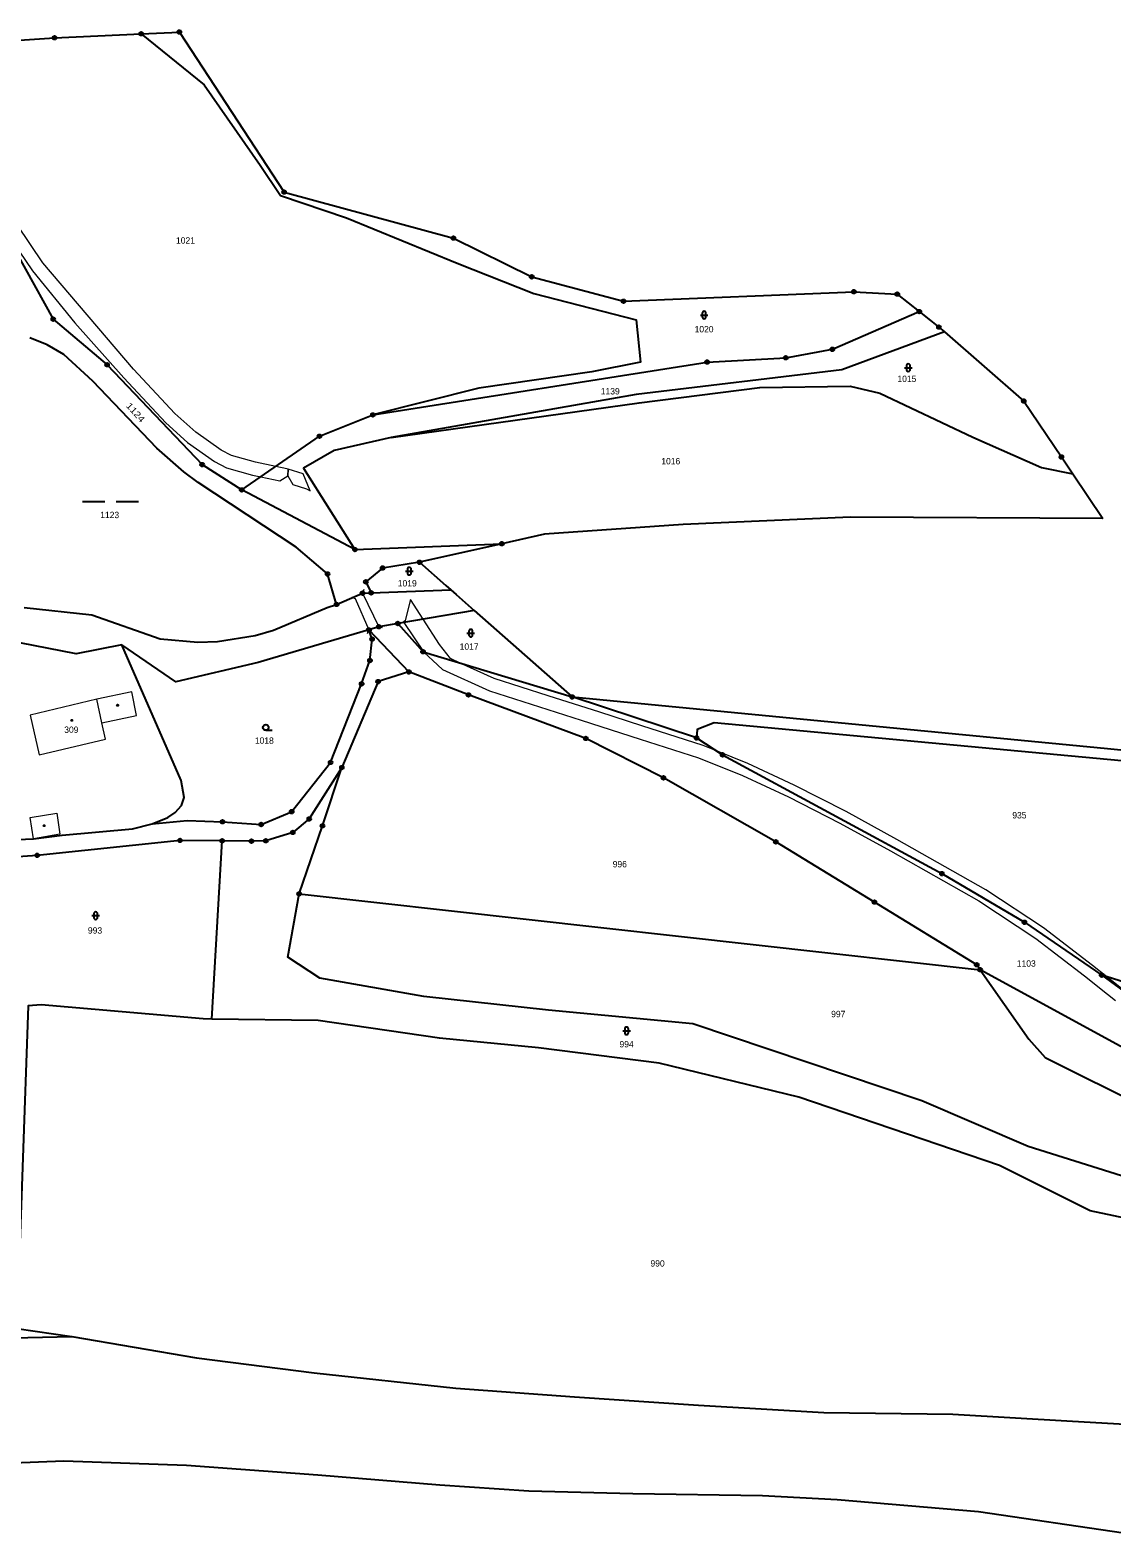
# Model space of a CAD drawing. Extents: x -758887 to -754328, y -1031688 to -1029144.
# Drawn here: x -757288.4 to -756999.4, y -1029651.7 to -1029248.7 of the extents above; entities that cross this region are included whole.
import ezdxf
from ezdxf.enums import TextEntityAlignment as Align

# ---------------------------------------------------------------- set-up
doc = ezdxf.new("R2010")
doc.units = 0
doc.header["$LTSCALE"] = 0.68
for name, color, linetype, lineweight in [('1', 7, 'Continuous', 25), ('13', 7, 'Continuous', 13), ('3', 7, 'Continuous', 25), ('4', 7, 'Continuous', 13), ('5', 7, 'Continuous', 25), ('8', 7, 'Continuous', 25)]:
    doc.layers.add(name, color=color, linetype=linetype, lineweight=lineweight)
doc.layers.add('2', color=7, linetype='Continuous')

msp = doc.modelspace()

# ---------------------------------------------------------------- linework, layer by layer
at = {"layer": '1'}
for p, q in [((-757050.84, -1029323.95), (-757047.83, -1029326.34)), ((-757047.83, -1029326.34), (-757045.61, -1029328.1)), ((-757045.61, -1029328.1), (-757044.12, -1029329.4)), ((-757201.64, -1029387.56), (-757231.92, -1029371.61)), ((-757201.64, -1029387.56), (-757162.39, -1029385.99)), ((-757184.38, -1029390.96), (-757177.34, -1029397.17)), ((-757177.34, -1029397.17), (-757176.07, -1029398.29)), ((-757197.3, -1029399.12), (-757176.07, -1029398.29)), ((-757176.07, -1029398.29), (-757174.58, -1029399.61)), ((-757174.58, -1029399.61), (-757169.82, -1029403.81)), ((-757169.82, -1029403.81), (-757190.2, -1029407.32)), ((-757169.82, -1029403.81), (-757157.88, -1029414.34)), ((-757197.9, -1029409.05), (-757187.23, -1029420.28)), ((-757157.88, -1029414.34), (-757143.59, -1029426.95)), ((-757110.36, -1029437.91), (-757143.59, -1029426.95)), ((-757239.88, -1029513.02), (-757237.12, -1029465.41)), ((-757216.56, -1029479.58), (-757034.58, -1029499.84)), ((-757292.02, -1029595.7), (-757277.31, -1029597.89))]:
    msp.add_line(p, q, dxfattribs=at)
for points in [[(-757304.11, -1029252.23), (-757303.67, -1029253.33), (-757322.82, -1029259.01), (-757313.65, -1029271.95), (-757297.2, -1029299.28), (-757282.28, -1029325.98), (-757267.89, -1029338.18), (-757242.47, -1029364.86), (-757231.92, -1029371.61)], [(-757299.48, -1029251.93), (-757281.9, -1029250.79), (-757258.78, -1029249.72), (-757248.58, -1029249.25)], [(-757258.78, -1029249.72), (-757241.93, -1029263.35), (-757226.99, -1029284.82), (-757221.56, -1029292.95), (-757203.95, -1029298.89), (-757174.34, -1029311.03), (-757153.81, -1029319.14), (-757126.48, -1029326.17), (-757125.36, -1029337.45), (-757138.34, -1029340.07), (-757168.55, -1029344.46), (-757196.86, -1029351.58)], [(-757248.58, -1029249.25), (-757220.58, -1029292.03), (-757175.35, -1029304.33), (-757154.42, -1029314.68), (-757129.85, -1029321.19), (-757068.31, -1029318.65), (-757056.72, -1029319.28), (-757050.84, -1029323.95)], [(-757196.86, -1029351.58), (-757107.55, -1029337.44), (-757086.54, -1029336.31), (-757074.07, -1029334.04), (-757050.84, -1029323.95)], [(-757206.55, -1029402.23), (-757208.97, -1029394.08), (-757217.36, -1029386.89), (-757243.54, -1029369.61), (-757247.42, -1029366.77), (-757254.6, -1029360.42), (-757271.72, -1029342.56), (-757279.41, -1029335.43), (-757283.91, -1029332.87), (-757288.52, -1029330.98)], [(-757044.12, -1029329.4), (-757071.58, -1029339.5), (-757126.54, -1029346.12), (-757191.98, -1029357.62)], [(-757044.12, -1029329.4), (-757022.92, -1029347.87), (-757012.87, -1029362.81), (-757009.83, -1029367.33), (-757001.8, -1029379.27)], [(-757191.98, -1029357.62), (-757125.67, -1029348.33), (-757093.49, -1029344.25), (-757069.31, -1029343.91), (-757061.36, -1029345.73), (-757036.53, -1029357.48), (-757018.22, -1029365.65), (-757009.83, -1029367.33)], [(-757231.92, -1029371.61), (-757211.13, -1029357.28), (-757196.86, -1029351.58)], [(-757191.98, -1029357.62), (-757207.23, -1029361.07), (-757215.41, -1029365.83), (-757201.64, -1029387.56)], [(-757001.8, -1029379.27), (-757069.25, -1029378.89), (-757113.94, -1029380.83), (-757151.03, -1029383.42), (-757162.39, -1029385.99), (-757184.38, -1029390.96)], [(-757184.38, -1029390.96), (-757194.26, -1029392.5), (-757198.75, -1029396.18), (-757197.3, -1029399.12)], [(-757206.55, -1029402.23), (-757199.64, -1029399.21), (-757197.3, -1029399.12)], [(-757290.03, -1029403.02), (-757271.98, -1029405.04), (-757253.73, -1029411.44), (-757243.64, -1029412.33), (-757238.42, -1029412.15), (-757228.35, -1029410.49), (-757223.45, -1029409.1), (-757209.09, -1029403.02), (-757206.55, -1029402.23)], [(-757197.9, -1029409.05), (-757227.51, -1029417.77), (-757249.48, -1029422.93), (-757263.96, -1029412.99)], [(-757255.83, -1029460.83), (-757246.49, -1029459.98), (-757237.04, -1029460.31), (-757226.71, -1029461.03), (-757218.57, -1029457.61), (-757208.17, -1029444.44), (-757199.86, -1029423.44), (-757197.64, -1029417.21), (-757197.07, -1029411.5), (-757197.9, -1029409.05)], [(-757190.2, -1029407.32), (-757195.23, -1029408.19), (-757197.9, -1029409.05)], [(-757190.2, -1029407.32), (-757183.46, -1029414.88), (-757143.59, -1029426.95)], [(-757263.96, -1029412.99), (-757276.11, -1029415.44), (-757291.2, -1029412.5)], [(-757255.83, -1029460.83), (-757251.67, -1029459.18), (-757249.73, -1029457.86), (-757248.03, -1029455.98), (-757247.33, -1029453.83), (-757248.07, -1029449.32), (-757263.96, -1029412.99)], [(-757187.23, -1029420.28), (-757195.47, -1029422.86), (-757205.14, -1029445.83)], [(-757034.58, -1029499.84), (-757035.5, -1029498.53), (-757062.84, -1029481.77), (-757089.2, -1029465.68), (-757119.21, -1029448.57), (-757139.97, -1029438.04), (-757171.31, -1029426.4), (-757187.23, -1029420.28)], [(-757143.59, -1029426.95), (-757000.54, -1029440.74), (-756946.71, -1029446.19)], [(-756972.53, -1029446.72), (-756996.8, -1029443.99), (-757105.63, -1029433.9), (-757110.21, -1029435.61), (-757110.36, -1029437.91)], [(-757110.36, -1029437.91), (-757103.39, -1029442.43), (-757044.8, -1029474.17), (-757022.74, -1029487.17), (-757002.1, -1029501.33)], [(-757205.14, -1029445.83), (-757213.86, -1029459.56), (-757218.24, -1029463.15), (-757225.44, -1029465.39), (-757229.33, -1029465.49), (-757237.12, -1029465.41)], [(-757216.56, -1029479.58), (-757210.32, -1029461.37), (-757205.14, -1029445.83)], [(-757327.38, -1029449.01), (-757325.45, -1029460.79), (-757318.86, -1029464.71), (-757313.97, -1029466.08), (-757302.55, -1029465.47), (-757287.55, -1029464.83), (-757279.89, -1029463.85), (-757261.13, -1029462.23), (-757255.83, -1029460.83)], [(-757237.12, -1029465.41), (-757248.4, -1029465.29), (-757286.55, -1029469.28), (-757304.49, -1029470.53)], [(-757034.58, -1029499.84), (-757021.6, -1029518.44), (-757017.17, -1029523.34), (-756989.85, -1029536.9), (-756971.03, -1029548.24), (-756956.93, -1029560.36), (-756960.24, -1029564.93), (-756993.65, -1029555.93), (-757021.76, -1029547.07), (-757050.12, -1029534.92), (-757111.37, -1029514.33), (-757149.95, -1029510.62), (-757183.23, -1029507.03), (-757211.07, -1029502.14), (-757219.61, -1029496.51), (-757216.56, -1029479.58)], [(-756859.56, -1029624.13), (-756926.38, -1029581.59), (-756952.01, -1029549.12), (-756983.48, -1029527.78), (-757034.58, -1029499.84)], [(-756933.02, -1029518.73), (-756939.65, -1029517.52), (-756973.86, -1029510.15), (-756977.93, -1029508.88), (-757002.1, -1029501.33)], [(-757002.1, -1029501.33), (-756988.14, -1029511.49), (-756966.39, -1029521.96), (-756951.73, -1029525.77)], [(-757239.88, -1029513.02), (-757242.22, -1029512.98), (-757285.51, -1029509.23), (-757288.95, -1029509.48), (-757292.02, -1029595.7)], [(-756859.56, -1029624.13), (-756878.5, -1029619.66), (-756905.38, -1029600.55), (-756934.02, -1029585.08), (-756957.96, -1029574.23), (-757005.2, -1029564.26), (-757029.41, -1029552.16), (-757083.07, -1029533.87), (-757120.35, -1029524.85), (-757152.6, -1029520.72), (-757179.08, -1029518.16), (-757211.51, -1029513.46), (-757239.88, -1029513.02)], [(-757606.43, -1029605.31), (-757441.87, -1029601.6), (-757277.31, -1029597.89)], [(-757277.31, -1029597.89), (-757243.97, -1029603.57), (-757212.59, -1029607.57), (-757174.69, -1029611.67), (-757142.99, -1029613.95), (-757109.82, -1029616.21), (-757076.36, -1029618.22), (-757041.86, -1029618.63), (-757009.86, -1029620.47), (-756989.63, -1029621.7), (-756930.92, -1029626.76), (-756879.95, -1029630.51), (-756863.82, -1029630.01), (-756854.23, -1029627.82)], [(-756857.49, -1029653.28), (-756888.68, -1029652.07), (-756936.06, -1029648.37), (-756955.79, -1029648.43), (-756996.27, -1029650.41), (-757034.99, -1029644.77), (-757072.79, -1029641.54), (-757092.75, -1029640.46), (-757127.36, -1029639.96), (-757155.18, -1029639.23), (-757178.97, -1029637.59), (-757211.55, -1029634.89), (-757246.63, -1029632.37), (-757279.49, -1029631.19), (-757315.6, -1029632.63)]]:
    msp.add_lwpolyline(points, dxfattribs=at)
at = {"layer": '13'}
for points in [[(-757294.79, -1029302.85), (-757287.83, -1029313.07), (-757276.55, -1029326.94), (-757263.4, -1029341.69), (-757252.23, -1029353.67), (-757246.38, -1029358.95), (-757239.18, -1029364.01), (-757235.97, -1029365.69), (-757229.07, -1029367.64), (-757226.83, -1029368.1), (-757221.73, -1029369.15), (-757219.58, -1029367.83), (-757219.46, -1029366.08), (-757219.86, -1029365.95), (-757222.83, -1029365.34), (-757228.25, -1029364.24), (-757234.67, -1029362.43), (-757237.36, -1029361.01), (-757244.2, -1029356.21), (-757249.77, -1029351.17), (-757260.82, -1029339.33), (-757285.03, -1029310.97), (-757291.87, -1029300.91)], [(-756996.33, -1029505.26), (-757000.26, -1029502.12), (-757000.7, -1029501.77), (-757002.1, -1029501.33), (-757022.74, -1029487.17), (-757044.8, -1029474.17), (-757103.39, -1029442.43), (-757105.05, -1029441.36), (-757108.62, -1029439.9), (-757124.99, -1029434.66), (-757136.21, -1029431.06), (-757149.98, -1029426.65), (-757164.44, -1029422.02), (-757173.53, -1029417.88), (-757183.28, -1029414.94), (-757183.16, -1029415.11), (-757180.88, -1029417.19), (-757178.22, -1029419.6), (-757165.7, -1029425.3), (-757141.23, -1029433.14), (-757125.44, -1029438.2), (-757109.82, -1029443.2), (-757098.09, -1029447.98), (-757085.76, -1029453.66), (-757072.04, -1029460.66), (-757058.55, -1029468.08), (-757034.92, -1029481.48), (-757019.67, -1029491.52), (-757006.69, -1029501.48), (-757000.52, -1029506.4), (-756998.39, -1029508.1)]]:
    msp.add_lwpolyline(points, dxfattribs=at)
for points in [[(-757215.52, -1029367.36), (-757219.46, -1029366.08), (-757219.58, -1029367.83), (-757218.27, -1029370.15), (-757214.63, -1029371.32), (-757213.64, -1029371.83)], [(-757173.53, -1029417.88), (-757176.14, -1029416.7), (-757179.09, -1029412.94), (-757183.46, -1029406.16), (-757186.83, -1029400.93), (-757187.95, -1029405.47), (-757188.24, -1029406.65), (-757188.67, -1029406.88), (-757188.56, -1029407.04), (-757183.28, -1029414.94)], [(-757105.05, -1029441.36), (-757103.39, -1029442.43), (-757044.8, -1029474.17), (-757022.74, -1029487.17), (-757002.1, -1029501.33), (-757000.7, -1029501.77), (-757004.53, -1029498.72), (-757017.65, -1029488.66), (-757033.1, -1029478.5), (-757056.85, -1029465.02), (-757070.4, -1029457.56), (-757084.24, -1029450.52), (-757096.69, -1029444.76)]]:
    msp.add_lwpolyline(points, close=True, dxfattribs=at)
at = {"layer": '3'}
for p, q in [((-757109.351, -1029324.881), (-757107.349, -1029324.881)), ((-757108.851, -1029324.381), (-757108.851, -1029325.382)), ((-757107.849, -1029325.382), (-757107.849, -1029324.381)), ((-757054.781, -1029338.961), (-757052.779, -1029338.961)), ((-757054.281, -1029338.461), (-757054.281, -1029339.462)), ((-757053.279, -1029339.462), (-757053.279, -1029338.461)), ((-757274.469, -1029374.73), (-757268.469, -1029374.73)), ((-757265.469, -1029374.73), (-757259.469, -1029374.73)), ((-757188.131, -1029393.331), (-757186.129, -1029393.331)), ((-757187.631, -1029392.831), (-757187.631, -1029393.832)), ((-757186.629, -1029393.832), (-757186.629, -1029392.831)), ((-757171.211, -1029409.391), (-757171.211, -1029410.392)), ((-757170.209, -1029410.392), (-757170.209, -1029409.391)), ((-757171.711, -1029409.891), (-757169.709, -1029409.891)), ((-757225.483, -1029435.85), (-757223.733, -1029435.85)), ((-757271.941, -1029485.391), (-757269.939, -1029485.391)), ((-757271.441, -1029484.891), (-757271.441, -1029485.892)), ((-757270.439, -1029485.892), (-757270.439, -1029484.891)), ((-757130.061, -1029516.181), (-757128.059, -1029516.181)), ((-757129.561, -1029515.681), (-757129.561, -1029516.682)), ((-757128.559, -1029516.682), (-757128.559, -1029515.681))]:
    msp.add_line(p, q, dxfattribs=at)
msp.add_circle((-757225.4829, -1029435.0998), 0.75, dxfattribs=at)
for centre, start, end in [((-757108.35, -1029324.3809), 0, 180), ((-757108.35, -1029325.3809), 180, 359.98789), ((-757053.78, -1029338.4609), 0, 180), ((-757053.78, -1029339.4609), 180, 359.98789), ((-757187.13, -1029392.8309), 0, 180), ((-757187.13, -1029393.8309), 180, 359.98789), ((-757170.71, -1029409.3909), 0, 180), ((-757170.71, -1029410.3909), 180, 359.98789), ((-757270.94, -1029484.8909), 0, 180), ((-757270.94, -1029485.8909), 180, 359.98789), ((-757129.06, -1029515.6809), 0, 180), ((-757129.06, -1029516.6809), 180, 359.98789)]:
    msp.add_arc(centre, 0.5, start, end, dxfattribs=at)
at = {"layer": '4'}
for p, q in [((-757202.534, -1029400.321), (-757201.6, -1029400.679)), ((-757201.6, -1029400.68), (-757197.9, -1029409.05)), ((-757199.64, -1029399.21), (-757195.23, -1029408.19)), ((-757199.314, -1029398.264), (-757199.639, -1029399.21)), ((-757198.259, -1029409.984), (-757197.901, -1029409.05)), ((-757194.284, -1029408.516), (-757195.23, -1029408.191)), ((-757261.28, -1029425.6), (-757270.67, -1029427.58)), ((-757269.26, -1029433.88), (-757270.67, -1029427.58))]:
    msp.add_line(p, q, dxfattribs=at)
for points in [[(-757269.26, -1029433.88), (-757260, -1029431.93), (-757261.28, -1029425.6)], [(-757270.67, -1029427.58), (-757288.44, -1029431.84), (-757286.03, -1029442.4), (-757268.28, -1029438.22), (-757269.26, -1029433.88)]]:
    msp.add_lwpolyline(points, dxfattribs=at)
msp.add_lwpolyline([(-757287.55, -1029464.83), (-757288.42, -1029459.2), (-757281.35, -1029457.99), (-757280.51, -1029463.63)], close=True, dxfattribs=at)
at = {"layer": '5'}
for centre in [(-757265.0668, -1029429.1592), (-757277.3168, -1029433.1992), (-757284.6968, -1029461.3492)]:
    msp.add_circle(centre, 0.175, dxfattribs=at)
at = {"layer": '8'}
for centre, radius in [((-757281.9, -1029250.7899), 0.5), ((-757281.9, -1029250.7899), 0.0303), ((-757258.78, -1029249.7199), 0.5), ((-757258.78, -1029249.7199), 0.0303), ((-757248.58, -1029249.2499), 0.5), ((-757248.58, -1029249.2499), 0.0303), ((-757220.58, -1029292.0299), 0.5), ((-757220.58, -1029292.0299), 0.0303), ((-757175.35, -1029304.3299), 0.5), ((-757175.35, -1029304.3299), 0.0303), ((-757154.42, -1029314.6799), 0.5), ((-757154.42, -1029314.6799), 0.0303), ((-757129.85, -1029321.1899), 0.5), ((-757068.31, -1029318.6499), 0.5), ((-757068.31, -1029318.6499), 0.0303), ((-757056.72, -1029319.2799), 0.5), ((-757056.72, -1029319.2799), 0.0303), ((-757129.85, -1029321.1899), 0.0303), ((-757050.84, -1029323.9499), 0.5), ((-757050.84, -1029323.9499), 0.0303), ((-757282.28, -1029325.9799), 0.5), ((-757282.28, -1029325.9799), 0.0303), ((-757045.61, -1029328.0999), 0.5), ((-757045.61, -1029328.0999), 0.0303), ((-757107.55, -1029337.4399), 0.5), ((-757086.54, -1029336.3099), 0.5), ((-757086.54, -1029336.3099), 0.0303), ((-757074.07, -1029334.0399), 0.5), ((-757074.07, -1029334.0399), 0.0303), ((-757267.89, -1029338.1799), 0.5), ((-757267.89, -1029338.1799), 0.0303), ((-757107.55, -1029337.4399), 0.0303), ((-757022.92, -1029347.8699), 0.5), ((-757022.92, -1029347.8699), 0.0303), ((-757196.86, -1029351.5799), 0.5), ((-757196.86, -1029351.5799), 0.0303), ((-757211.13, -1029357.2799), 0.5), ((-757211.13, -1029357.2799), 0.0303), ((-757242.47, -1029364.8599), 0.5), ((-757242.47, -1029364.8599), 0.0303), ((-757012.87, -1029362.8099), 0.5), ((-757012.87, -1029362.8099), 0.0303), ((-757231.92, -1029371.6099), 0.5), ((-757231.92, -1029371.6099), 0.0303), ((-757162.39, -1029385.9899), 0.5), ((-757201.64, -1029387.5599), 0.5), ((-757201.64, -1029387.5599), 0.0303), ((-757162.39, -1029385.9899), 0.0303), ((-757208.97, -1029394.0799), 0.5), ((-757194.26, -1029392.4999), 0.5), ((-757194.26, -1029392.4999), 0.0303), ((-757184.38, -1029390.9599), 0.5), ((-757184.38, -1029390.9599), 0.0303), ((-757208.97, -1029394.0799), 0.0303), ((-757198.75, -1029396.1799), 0.5), ((-757198.75, -1029396.1799), 0.0303), ((-757199.64, -1029399.2099), 0.5), ((-757199.64, -1029399.2099), 0.0303), ((-757197.3, -1029399.1199), 0.5), ((-757197.3, -1029399.1199), 0.0303), ((-757206.55, -1029402.2299), 0.5), ((-757206.55, -1029402.2299), 0.0303), ((-757197.9, -1029409.0499), 0.5), ((-757197.9, -1029409.0499), 0.0303), ((-757195.23, -1029408.1899), 0.5), ((-757195.23, -1029408.1899), 0.0303), ((-757190.2, -1029407.3199), 0.5), ((-757190.2, -1029407.3199), 0.0303), ((-757197.07, -1029411.4999), 0.5), ((-757197.07, -1029411.4999), 0.0303), ((-757197.64, -1029417.2099), 0.5), ((-757197.64, -1029417.2099), 0.0303), ((-757183.46, -1029414.8799), 0.5), ((-757183.46, -1029414.8799), 0.0303), ((-757187.23, -1029420.2799), 0.5), ((-757187.23, -1029420.2799), 0.0303), ((-757199.86, -1029423.4399), 0.5), ((-757199.86, -1029423.4399), 0.0303), ((-757195.47, -1029422.8599), 0.5), ((-757195.47, -1029422.8599), 0.0303), ((-757171.31, -1029426.3999), 0.5), ((-757171.31, -1029426.3999), 0.0303), ((-757143.59, -1029426.9499), 0.5), ((-757143.59, -1029426.9499), 0.0303), ((-757139.97, -1029438.0399), 0.5), ((-757110.36, -1029437.9099), 0.5), ((-757110.36, -1029437.9099), 0.0303), ((-757139.97, -1029438.0399), 0.0303), ((-757103.39, -1029442.4299), 0.5), ((-757208.17, -1029444.4399), 0.5), ((-757208.17, -1029444.4399), 0.0303), ((-757205.14, -1029445.8299), 0.5), ((-757205.14, -1029445.8299), 0.0303), ((-757103.39, -1029442.4299), 0.0303), ((-757119.21, -1029448.5699), 0.5), ((-757119.21, -1029448.5699), 0.0303), ((-757218.57, -1029457.6099), 0.5), ((-757218.57, -1029457.6099), 0.0303), ((-757237.04, -1029460.3099), 0.5), ((-757237.04, -1029460.3099), 0.0303), ((-757226.71, -1029461.0299), 0.5), ((-757226.71, -1029461.0299), 0.0303), ((-757213.86, -1029459.5599), 0.5), ((-757213.86, -1029459.5599), 0.0303), ((-757210.32, -1029461.3699), 0.5), ((-757210.32, -1029461.3699), 0.0303), ((-757248.4, -1029465.2899), 0.5), ((-757248.4, -1029465.2899), 0.0303), ((-757237.12, -1029465.4099), 0.5), ((-757237.12, -1029465.4099), 0.0303), ((-757229.33, -1029465.4899), 0.5), ((-757229.33, -1029465.4899), 0.0303), ((-757225.44, -1029465.3899), 0.5), ((-757225.44, -1029465.3899), 0.0303), ((-757218.24, -1029463.1499), 0.5), ((-757218.24, -1029463.1499), 0.0303), ((-757089.2, -1029465.6799), 0.5), ((-757089.2, -1029465.6799), 0.0303), ((-757286.55, -1029469.2799), 0.5), ((-757286.55, -1029469.2799), 0.0303), ((-757044.8, -1029474.1699), 0.5), ((-757044.8, -1029474.1699), 0.0303), ((-757216.56, -1029479.5799), 0.5), ((-757216.56, -1029479.5799), 0.0303), ((-757062.84, -1029481.7699), 0.5), ((-757062.84, -1029481.7699), 0.0303), ((-757022.74, -1029487.1699), 0.5), ((-757022.74, -1029487.1699), 0.0303), ((-757035.5, -1029498.5299), 0.5), ((-757035.5, -1029498.5299), 0.0303), ((-757034.58, -1029499.8399), 0.5), ((-757034.58, -1029499.8399), 0.0303), ((-757002.1, -1029501.3299), 0.5), ((-757002.1, -1029501.3299), 0.0303)]:
    msp.add_circle(centre, radius, dxfattribs=at)

# ---------------------------------------------------------------- texts
at = {"layer": '2'}
for s, p in [('1021', (-757246.94, -1029305.796)), ('1020', (-757108.35, -1029329.516)), ('1015', (-757054.16, -1029342.776)), ('1139', (-757133.43, -1029346.106)), ('1016', (-757117.25, -1029364.796)), ('1123', (-757267.19, -1029379.166)), ('1019', (-757187.67, -1029397.426)), ('1017', (-757171.14, -1029414.346)), ('309', (-757277.439, -1029436.556)), ('1018', (-757225.87, -1029439.466)), ('935', (-757024.089, -1029459.416)), ('996', (-757130.879, -1029472.486)), ('993', (-757271.109, -1029490.206)), ('1103', (-757022.25, -1029499.036)), ('997', (-757072.489, -1029512.536)), ('994', (-757129.059, -1029520.606)), ('990', (-757120.779, -1029579.176))]:
    msp.add_text(s, height=1.7, dxfattribs=at).set_placement(p, align=Align.CENTER)
at = {"layer": '2', "width": 1.2}
msp.add_text('1124', height=1.7, rotation=312, dxfattribs=at).set_placement((-757260.9211, -1029351.4862), align=Align.CENTER)

doc.saveas('drawing.dxf')
